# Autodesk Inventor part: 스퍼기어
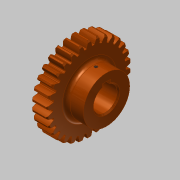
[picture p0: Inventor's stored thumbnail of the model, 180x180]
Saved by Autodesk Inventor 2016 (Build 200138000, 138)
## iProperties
Created: 2019-01
Part Number: 스퍼기어
Material: 알루미늄 6061
Document SubType Name: Modeling
Designer: mduedu
Density: 1 g/cm^3
Appearance: 매끄러움 - 연한 주황색
Author: mduedu
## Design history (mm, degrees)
sketch "스케치1"
  geometry: C1 r 27.5 at (0, 0); 1 further point
  constraints: 1 centre point, 1 coincident
  dimensions: "d0" = 55 diameter of C1
extrude "돌출1" new body sketch "스케치1" stored distance "d2" = 12; taper "d3" = 0 deg
sketch "스케치2" dims "d4" = 60
  geometry: L1 (0, 0)-(-32, 0); L2 (0, 0)-(0, 32); L3 (-0.57, 0)-(-0.57, 31.995); L4 (-1.57, 0)-(-1.57, 31.961); L5 (-2.07, 0)-(-2.07, 31.933); C1 r 27.5 at (0, 0); A1 r 32 centre (0, 0) between (-32, 0) and (0, 32); A2 r 9.292 centre (7.208, 26.911) between (-0.57, 31.995) and (-2.07, 27.422); A3 r 9.292 centre (-7.208, 26.911) between (2.07, 27.422) and (0.57, 31.995); A4 r 27.5 centre (0, 0) between (2.07, 27.422) and (-2.07, 27.422); A5 r 32 centre (0, 0) between (0.57, 31.995) and (-0.57, 31.995); 3 further points
  constraints: 14 point on circle, 10 end point, 6 centre point, 5 coincident, 5 point on line, 3 symmetric about line, 2 parallel, 2 perpendicular, 1 horizontal, 7 other
  dimensions: "d6" = 64 diameter of A1; "d7" = 0.5 distance between parallel lines of L4 L5; "d8" = 1 distance between parallel lines of L3 L4; "d9" = 1.57 distance between parallel lines of L2 L4
extrude "돌출2" join sketch "스케치2" stored distance "d10" = 0; taper "d11" = 0 deg
chamfer "모따기1" distance "d12" = 1; stored, may be unused: second distance "d13" = 2, angle "d14" = 45 deg
fillet "모깎기1" dims "d15" = 0.5
sketch "스케치3"
  geometry: C1 r 17.5 at (0, 0); 1 further point
  constraints: 1 centre point, 1 coincident
  dimensions: "d19" = 35 diameter of C1
extrude "돌출3" join sketch "스케치3" distance "d20" = 13; taper "d21" = 0 deg
sketch "스케치4"
  geometry: L1 (-3, 8.485)-(3, 8.485); L2 (3, 8.485)-(3, 11.8); L3 (3, 11.8)-(-3, 11.8); L4 (-3, 11.8)-(-3, 8.485); A1 r 9 centre (0, 0) between (-3, 8.485) and (3, 8.485); 1 further point
  constraints: 8 end point, 2 parallel, 2 point on circle, 1 centre point, 1 coincident, 1 horizontal, 1 perpendicular
  dimensions: "d22" = 18 diameter of A1; "d23" = 6 distance of L2.end L3.end; "d24" = 20.8 dimension on A1 L3
extrude "돌출4" cut sketch "스케치4" stored distance "d25" = 13; taper "d26" = 0 deg
sketch "스케치5"
  geometry: C1 r 15 at (0, 0); C2 r 22.5 at (0, 0); 1 further point
  constraints: 2 centre point, 2 coincident
  dimensions: "d33" = 30 diameter of C1; "d34" = 45 diameter of C2
extrude "돌출5" cut sketch "스케치5" distance "d30" = 6; taper "d31" = 0 deg
fillet "모깎기2" dims "d32" = 3
node "작업 평면1"
sketch "스케치6"
  geometry: L1 (17.5, 13)-(-17.5, 13) reference; 2 further points
  constraints: 1 vertical alignment
  dimensions: "d35" = 8 distance from line of point (0, 5) L1
hole "구멍1" sketch "스케치6" at (0, 5) diameter "d36" = 2.459; stored, may be unused: countersink angle "d40" = 90 deg, drill point angle "d42" = 118 deg; dims "d37" = 6, "d38" = 4, "d39" = 2, "d41" = 8
fillet "모깎기3" dims "d43" = 3
chamfer "모따기2" distance "d44" = 1; stored, may be unused: second distance "d45" = 2, angle "d46" = 45 deg
node "솔리드1"
pattern_circular "원형 패턴1" dims "d17" = 360 deg
